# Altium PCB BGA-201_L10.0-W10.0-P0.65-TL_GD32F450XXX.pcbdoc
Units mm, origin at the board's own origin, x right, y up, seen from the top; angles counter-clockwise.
Board outline 23.08 x 23.08 mm, 2 copper layers (Top Layer, Bottom Layer), stack 0 mm thick; 1 components, 0 nets, 201 pads, 0 vias.
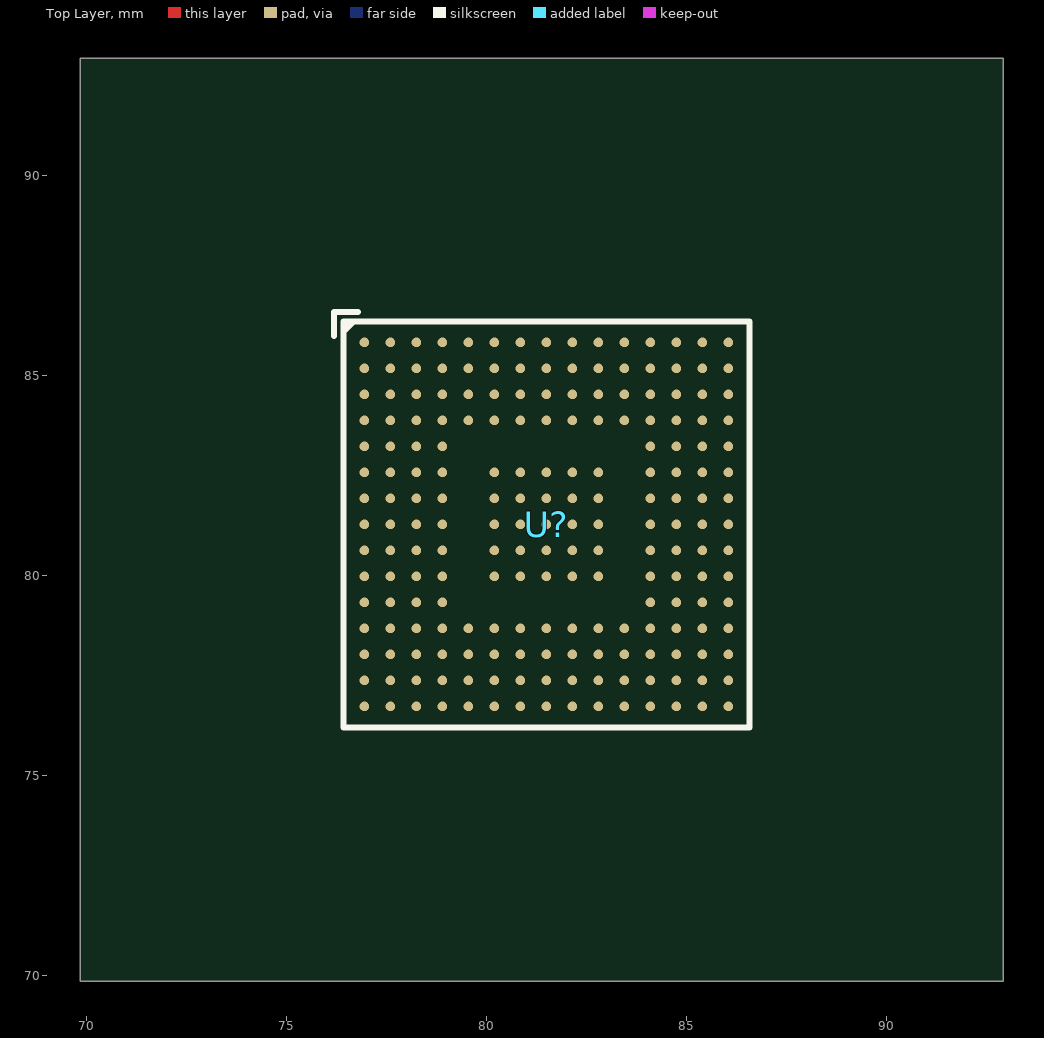
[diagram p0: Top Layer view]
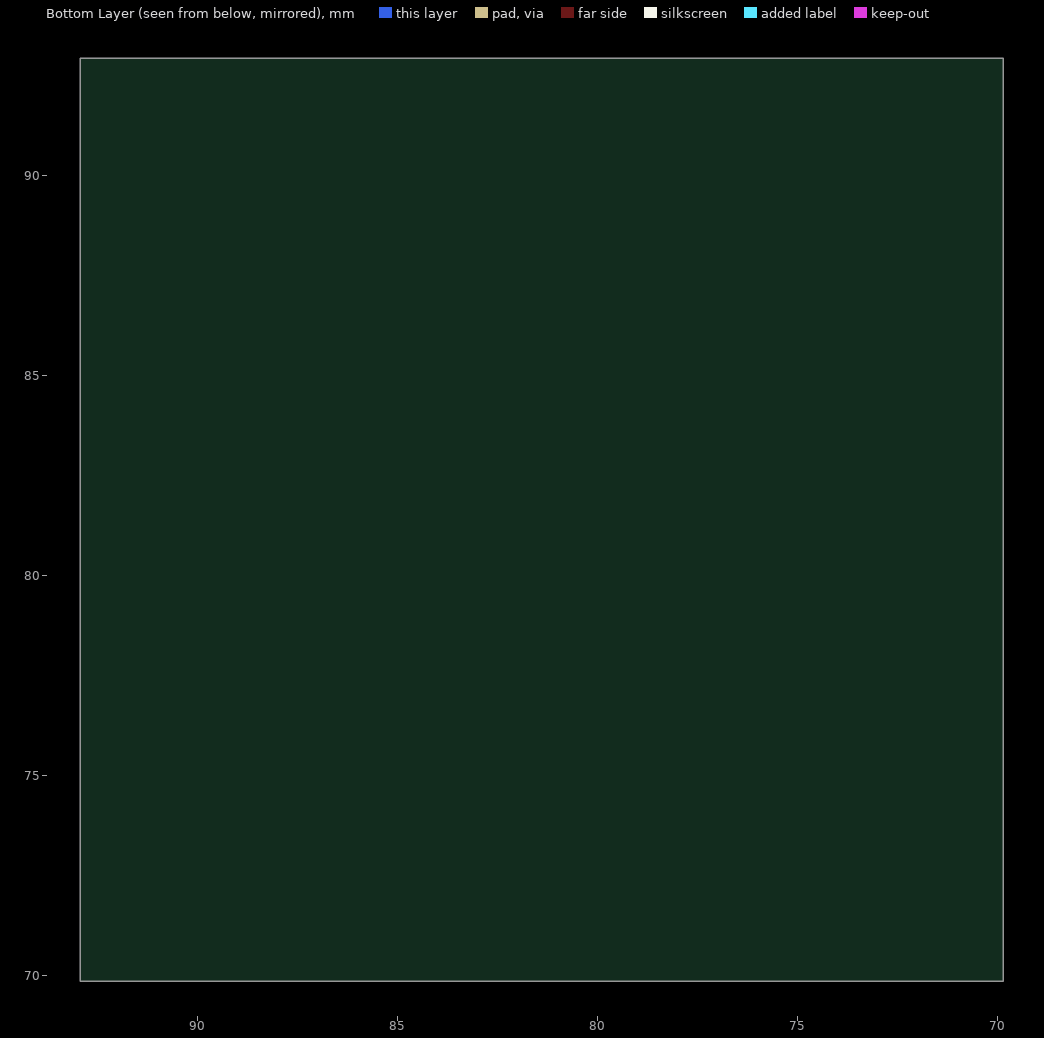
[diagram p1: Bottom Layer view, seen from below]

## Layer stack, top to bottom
Top Layer: signal copper (thickness not stored)
Bottom Layer: signal copper (thickness not stored)

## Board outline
92.931,69.85 69.85,69.85 69.85,92.931 92.931,92.931

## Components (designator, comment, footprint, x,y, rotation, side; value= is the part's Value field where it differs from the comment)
U? "" BGA-201_L10.0-W10.0-P0.65-TL_GD32F450XXX 81.505,81.276 r0 top

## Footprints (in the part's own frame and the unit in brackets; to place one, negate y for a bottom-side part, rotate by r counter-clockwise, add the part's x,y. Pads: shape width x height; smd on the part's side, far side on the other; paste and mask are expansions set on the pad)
BGA-201_L10.0-W10.0-P0.65-TL_GD32F450XXX [mm]
  round 0.24 smd paste-100 mask+0.051: A1(-4.55,4.55) A2(-3.9,4.55) A3(-3.25,4.55) A4(-2.6,4.55) A5(-1.95,4.55) A6(-1.3,4.55) A7(-0.65,4.55) A8(0,4.55) A9(0.65,4.55) A10(1.3,4.55) A11(1.95,4.55) A12(2.6,4.55) A13(3.25,4.55) A14(3.9,4.55) A15(4.55,4.55) B1(-4.55,3.9) B2(-3.9,3.9) B3(-3.25,3.9) B4(-2.6,3.9) B5(-1.95,3.9) B6(-1.3,3.9) B7(-0.65,3.9) B8(0,3.9) B9(0.65,3.9) B10(1.3,3.9) B11(1.95,3.9) B12(2.6,3.9) B13(3.25,3.9) B14(3.9,3.9) B15(4.55,3.9) C1(-4.55,3.25) C2(-3.9,3.25) C3(-3.25,3.25) C4(-2.6,3.25) C5(-1.95,3.25) C6(-1.3,3.25) C7(-0.65,3.25) C8(0,3.25) C9(0.65,3.25) C10(1.3,3.25) C11(1.95,3.25) C12(2.6,3.25) C13(3.25,3.25) C14(3.9,3.25) C15(4.55,3.25) D1(-4.55,2.6) D2(-3.9,2.6) D3(-3.25,2.6) D4(-2.6,2.6) D5(-1.95,2.6) D6(-1.3,2.6) D7(-0.65,2.6) D8(0,2.6) D9(0.65,2.6) D10(1.3,2.6) D11(1.95,2.6) D12(2.6,2.6) D13(3.25,2.6) D14(3.9,2.6) D15(4.55,2.6) E1(-4.55,1.95) E2(-3.9,1.95) E3(-3.25,1.95) E4(-2.6,1.95) E12(2.6,1.95) E13(3.25,1.95) E14(3.9,1.95) E15(4.55,1.95) F1(-4.55,1.3) F2(-3.9,1.3) F3(-3.25,1.3) F4(-2.6,1.3) F6(-1.3,1.3) F7(-0.65,1.3) F8(0,1.3) F9(0.65,1.3) F10(1.3,1.3) F12(2.6,1.3) F13(3.25,1.3) F14(3.9,1.3) F15(4.55,1.3) G1(-4.55,0.65) G2(-3.9,0.65) G3(-3.25,0.65) G4(-2.6,0.65) G6(-1.3,0.65) G7(-0.65,0.65) G8(0,0.65) G9(0.65,0.65) G10(1.3,0.65) G12(2.6,0.65) G13(3.25,0.65) G14(3.9,0.65) G15(4.55,0.65) H1(-4.55,0) H2(-3.9,0) H3(-3.25,0) H4(-2.6,0) H6(-1.3,0) H7(-0.65,0) H8(0,0) H9(0.65,0) H10(1.3,0) H12(2.6,0) H13(3.25,0) H14(3.9,0) H15(4.55,0) J1(-4.55,-0.65) J2(-3.9,-0.65) J3(-3.25,-0.65) J4(-2.6,-0.65) J6(-1.3,-0.65) J7(-0.65,-0.65) J8(0,-0.65) J9(0.65,-0.65) J10(1.3,-0.65) J12(2.6,-0.65) J13(3.25,-0.65) J14(3.9,-0.65) J15(4.55,-0.65) K1(-4.55,-1.3) K2(-3.9,-1.3) K3(-3.25,-1.3) K4(-2.6,-1.3) K6(-1.3,-1.3) K7(-0.65,-1.3) K8(0,-1.3) K9(0.65,-1.3) K10(1.3,-1.3) K12(2.6,-1.3) K13(3.25,-1.3) K14(3.9,-1.3) K15(4.55,-1.3) L1(-4.55,-1.95) L2(-3.9,-1.95) L3(-3.25,-1.95) L4(-2.6,-1.95) L12(2.6,-1.95) L13(3.25,-1.95) L14(3.9,-1.95) L15(4.55,-1.95) M1(-4.55,-2.6) M2(-3.9,-2.6) M3(-3.25,-2.6) M4(-2.6,-2.6) M5(-1.95,-2.6) M6(-1.3,-2.6) M7(-0.65,-2.6) M8(0,-2.6) M9(0.65,-2.6) M10(1.3,-2.6) M11(1.95,-2.6) M12(2.6,-2.6) M13(3.25,-2.6) M14(3.9,-2.6) M15(4.55,-2.6) N1(-4.55,-3.25) N2(-3.9,-3.25) N3(-3.25,-3.25) N4(-2.6,-3.25) N5(-1.95,-3.25) N6(-1.3,-3.25) N7(-0.65,-3.25) N8(0,-3.25) N9(0.65,-3.25) N10(1.3,-3.25) N11(1.95,-3.25) N12(2.6,-3.25) N13(3.25,-3.25) N14(3.9,-3.25) N15(4.55,-3.25) P1(-4.55,-3.9) P2(-3.9,-3.9) P3(-3.25,-3.9) P4(-2.6,-3.9) P5(-1.95,-3.9) P6(-1.3,-3.9) P7(-0.65,-3.9) P8(0,-3.9) P9(0.65,-3.9) P10(1.3,-3.9) P11(1.95,-3.9) P12(2.6,-3.9) P13(3.25,-3.9) P14(3.9,-3.9) P15(4.55,-3.9) R1(-4.55,-4.55) R2(-3.9,-4.55) R3(-3.25,-4.55) R4(-2.6,-4.55) R5(-1.95,-4.55) R6(-1.3,-4.55) R7(-0.65,-4.55) R8(0,-4.55) R9(0.65,-4.55) R10(1.3,-4.55) R11(1.95,-4.55) R12(2.6,-4.55) R13(3.25,-4.55) R14(3.9,-4.55) R15(4.55,-4.55)
  silkscreen extent -5.3,-5.08 5.08,5.3

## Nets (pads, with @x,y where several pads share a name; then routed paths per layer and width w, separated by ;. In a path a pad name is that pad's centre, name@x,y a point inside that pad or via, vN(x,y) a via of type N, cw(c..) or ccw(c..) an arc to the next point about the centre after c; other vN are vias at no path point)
pads on no net: U?.A1 U?.A2 U?.A3 U?.A4 U?.A5 U?.A6 U?.A7 U?.A8 U?.A9 U?.A10 U?.A11 U?.A12 U?.A13 U?.A14 U?.A15 U?.B1 U?.B2 U?.B3 U?.B4 U?.B5 U?.B6 U?.B7 U?.B8 U?.B9 U?.B10 U?.B11 U?.B12 U?.B13 U?.B14 U?.B15 U?.C1 U?.C2 U?.C3 U?.C4 U?.C5 U?.C6 U?.C7 U?.C8 U?.C9 U?.C10 U?.C11 U?.C12 U?.C13 U?.C14 U?.C15 U?.D1 U?.D2 U?.D3 U?.D4 U?.D5 U?.D6 U?.D7 U?.D8 U?.D9 U?.D10 U?.D11 U?.D12 U?.D13 U?.D14 U?.D15 U?.E1 U?.E2 U?.E3 U?.E4 U?.E12 U?.E13 U?.E14 U?.E15 U?.F1 U?.F2 U?.F3 U?.F4 U?.F6 U?.F7 U?.F8 U?.F9 U?.F10 U?.F12 U?.F13 U?.F14 U?.F15 U?.G1 U?.G2 U?.G3 U?.G4 U?.G6 U?.G7 U?.G8 U?.G9 U?.G10 U?.G12 U?.G13 U?.G14 U?.G15 U?.H1 U?.H2 U?.H3 U?.H4 U?.H6 U?.H7 U?.H8 U?.H9 U?.H10 U?.H12 U?.H13 U?.H14 U?.H15 U?.J1 U?.J2 U?.J3 U?.J4 U?.J6 U?.J7 U?.J8 U?.J9 U?.J10 U?.J12 U?.J13 U?.J14 U?.J15 U?.K1 U?.K2 U?.K3 U?.K4 U?.K6 U?.K7 U?.K8 U?.K9 U?.K10 U?.K12 U?.K13 U?.K14 U?.K15 U?.L1 U?.L2 U?.L3 U?.L4 U?.L12 U?.L13 U?.L14 U?.L15 U?.M1 U?.M2 U?.M3 U?.M4 U?.M5 U?.M6 U?.M7 U?.M8 U?.M9 U?.M10 U?.M11 U?.M12 U?.M13 U?.M14 U?.M15 U?.N1 U?.N2 U?.N3 U?.N4 U?.N5 U?.N6 U?.N7 U?.N8 U?.N9 U?.N10 U?.N11 U?.N12 U?.N13 U?.N14 U?.N15 U?.P1 U?.P2 U?.P3 U?.P4 U?.P5 U?.P6 U?.P7 U?.P8 U?.P9 U?.P10 U?.P11 U?.P12 U?.P13 U?.P14 U?.P15 U?.R1 U?.R2 U?.R3 U?.R4 U?.R5 U?.R6 U?.R7 U?.R8 U?.R9 U?.R10 U?.R11 U?.R12 U?.R13 U?.R14 U?.R15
